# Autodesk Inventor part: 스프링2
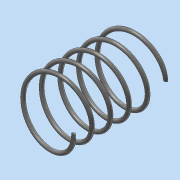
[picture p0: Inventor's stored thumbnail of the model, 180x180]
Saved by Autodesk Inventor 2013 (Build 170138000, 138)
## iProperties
Created: 2015-11
Part Number: 스프링2
Material: 강철, 탄소
Document SubType Name: Modeling
Designer: dgall
Density: 7.87 g/cm^3
Mass: 1.48972 g
Surface Area: 7.67135 cm^2
Volume: 0.189291 cm^3
Author: dgall
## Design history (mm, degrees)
sketch "스케치1"
  geometry: L1 (0, 0)-(8, 0); L2 (0, 0)-(0, 26); L3 (0, 26)-(8, 26); C1 r 0.5 at (8, 0)
  constraints: 6 end point, 2 perpendicular, 1 centre point, 1 coincident, 1 horizontal, 1 vertical alignment
  dimensions: "d0" = 16 diameter of L1.end L2; "d2" = 26 distance of L1.start L2.end (derived); "d3" = 1 diameter of C1
feature "코일1" sketch "스케치1" pitch "d4" = 10; turns "d6" = 5; dims "d5" = 26 (= d2), "d7" = 0, angle "d8" = 90 deg, angle "d9" = 90 deg, "d10" = 0, "d11" = 0
node "작업 평면1"
feature "분할1"
feature "분할2"
node "솔리드1"
other parameters: "d12" = 25
